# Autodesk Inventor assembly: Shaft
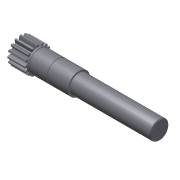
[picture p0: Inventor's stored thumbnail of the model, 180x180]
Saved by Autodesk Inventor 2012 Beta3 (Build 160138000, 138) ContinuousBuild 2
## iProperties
Created: 2010-12
Part Number: Shaft
Document SubType Name: Assembly
Designer: Thom Tremblay
ClientObjectVersion: 1
Author: Thom Tremblay
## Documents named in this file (2)
- C:\Inventor 2012 Essentials\Assemblies\Chapter 6\c6-01\Design Accelerator\Shaft5.iam
- C:\Inventor 2012 Essentials\Assemblies\Chapter 6\c6-01\Design Accelerator\Shaft5.ipt
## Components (1 placed, 1 different names)
1. Shaft:1
